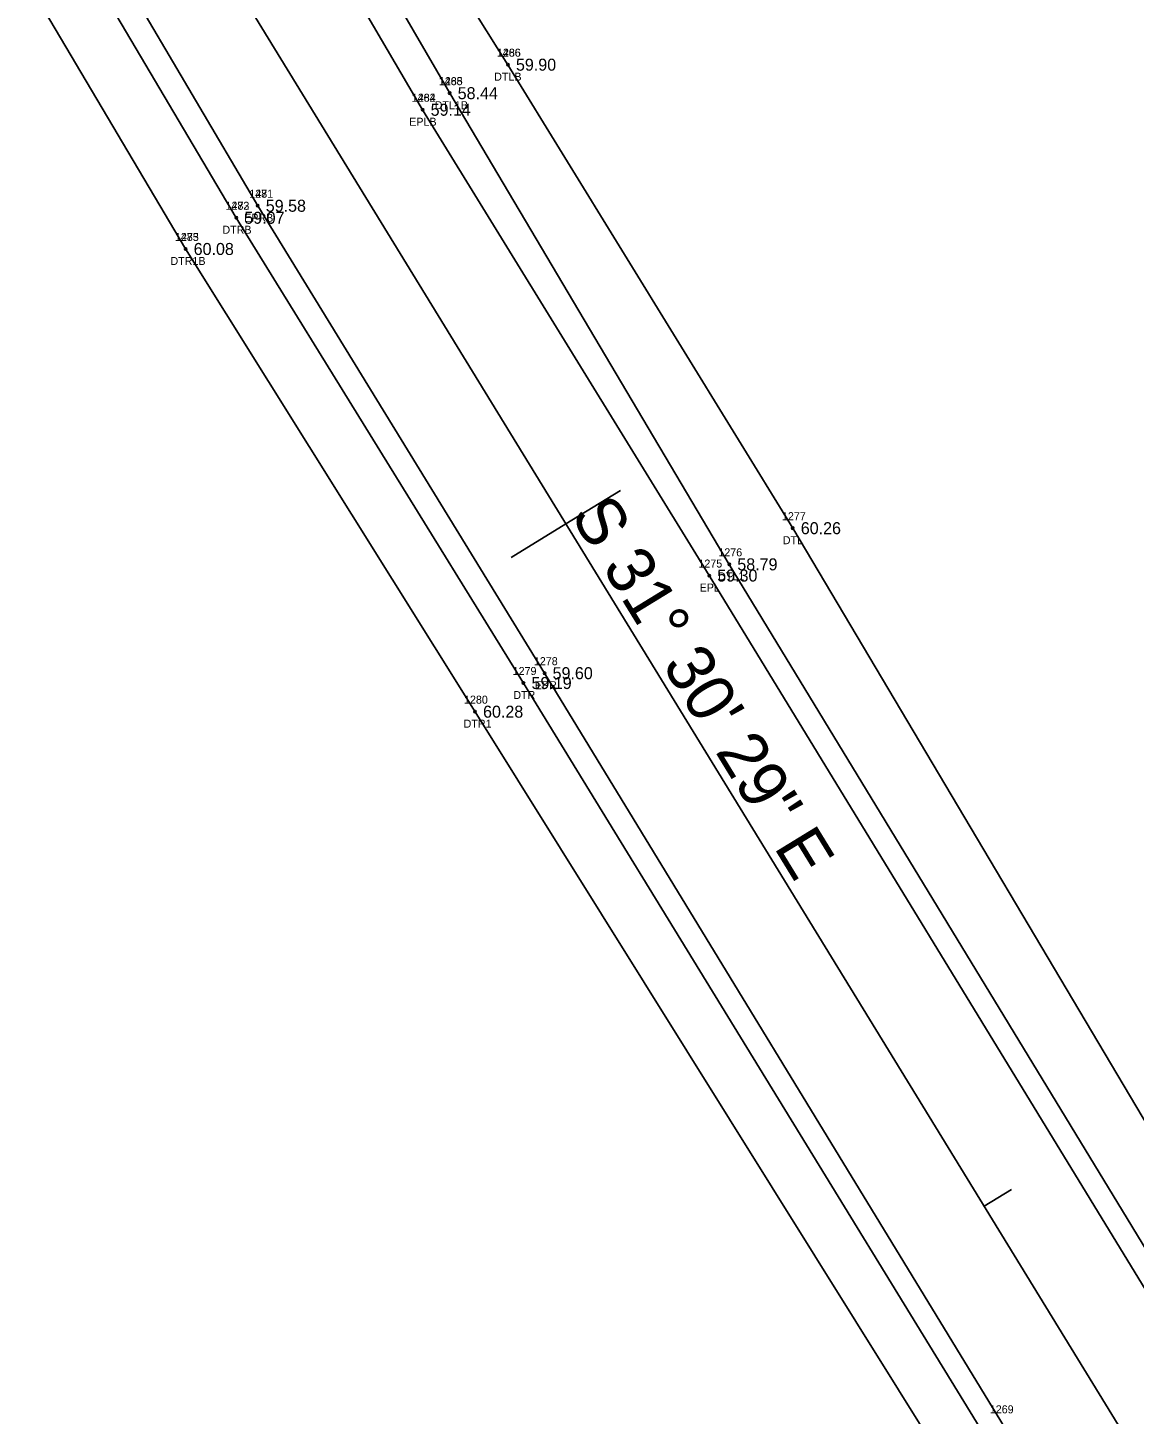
# Model space of a CAD drawing. Extents: x 2396531 to 2397633, y 770203 to 772837.
# Drawn here: x 2397231.4 to 2397369.7, y 770713.7 to 770887 of the extents above; entities that cross this region are included whole.
import ezdxf

# ---------------------------------------------------------------- set-up
doc = ezdxf.new("R2010")
doc.units = 0
for name, color, linetype in [('RD_EX_H2O', 7, 'Continuous'), ('RD_EX_H2O_txCode', 7, 'Continuous'), ('RD_EX_Road', 7, 'Continuous'), ('RD_EX_Road_txCode', 7, 'Continuous'), ('RD_EX_TX_H2O_ELEV', 7, 'Continuous'), ('RD_EX_TX_Road_ELEV', 7, 'Continuous'), ('RD_HC_Cl', 7, 'Continuous'), ('RD_HC_Data', 7, 'Continuous'), ('RD_HC_Data_Tic', 7, 'Continuous'), ('RD_SMD_Locator', 7, 'Continuous')]:
    doc.layers.add(name, color=color, linetype=linetype)

msp = doc.modelspace()

# ---------------------------------------------------------------- linework, layer by layer
at = {"layer": 'RD_EX_H2O'}
msp.add_line((2397255.92, 770938.9), (2397291.42, 770882.36), dxfattribs=at)
for points in [[(2397108.85, 771101.86), (2397130.27, 771108.67), (2397157.99, 771046.03), (2397184.53, 770991.63), (2397224.53, 770918.86), (2397257.48, 770863.23)], [(2397108.85, 771101.86), (2397123.52, 771093.58), (2397147.97, 771040.86), (2397177.5, 770986.79), (2397217.86, 770915.5), (2397251.15, 770859.33)], [(2397255.92, 770938.9), (2397250.75, 770936.23), (2397284.14, 770878.8)], [(2397586.15, 770211.51), (2397567.31, 770287.61), (2397548.79, 770357.79), (2397525.19, 770434.22), (2397495.53, 770510.39), (2397465.51, 770576.5), (2397430.55, 770645.5), (2397380.29, 770734.7), (2397327.01, 770824.44), (2397291.42, 770882.36)], [(2397579.43, 770209.93), (2397561.1, 770285.3), (2397543.19, 770356.19), (2397518.98, 770431.67), (2397489.88, 770507.8), (2397460.56, 770573.86), (2397425.02, 770642.83), (2397373.6, 770730.3), (2397319.08, 770819.92), (2397284.14, 770878.8)], [(2397432.83, 770561.85), (2397399.16, 770627.27), (2397350.75, 770711.42), (2397293.36, 770805.09), (2397257.48, 770863.23)], [(2397432.83, 770561.85), (2397426.86, 770559.56), (2397394.23, 770624.59), (2397345.55, 770708.21), (2397287.31, 770801.51), (2397251.15, 770859.33)]]:
    msp.add_lwpolyline(points, dxfattribs=at)
at = {"layer": 'RD_EX_Road'}
for points in [[(2397113.76, 771228.75), (2397130.87, 771177.98), (2397154.19, 771118.49), (2397170.38, 771081.25), (2397178.53, 771063.49), (2397207.96, 771004.56), (2397238.54, 770949.11), (2397245.72, 770936.59), (2397280.76, 770876.73)], [(2397093.16, 771212.62), (2397108.35, 771171.65), (2397122.66, 771133.29), (2397131.66, 771109.5), (2397159.86, 771046.96), (2397187.02, 770992.86), (2397227.29, 770920.43), (2397260.16, 770864.73)], [(2397576.88, 770209.21), (2397558.85, 770284.47), (2397539.93, 770354.87), (2397515.81, 770430.13), (2397486.97, 770506.75), (2397457.82, 770572.7), (2397422.37, 770641.75), (2397371.16, 770729.12), (2397316.57, 770818.52), (2397280.76, 770876.73)], [(2397553.19, 770205.48), (2397535.12, 770280.96), (2397517, 770349.24), (2397493.4, 770422.78), (2397467.13, 770492.9), (2397441.16, 770551.74), (2397436.66, 770561.67), (2397402.21, 770629.28), (2397353, 770712.83), (2397296, 770806.32), (2397260.16, 770864.73)]]:
    msp.add_lwpolyline(points, dxfattribs=at)
at = {"layer": 'RD_HC_Cl'}
msp.add_line((2397257.22, 770892.58), (2397369.44, 770709.51), dxfattribs=at)
at = {"layer": 'RD_HC_Data_Tic'}
for p, q in [((2397298.66, 770824.97), (2397305.48, 770829.15)), ((2397298.66, 770824.97), (2397291.84, 770820.79)), ((2397350.92, 770739.72), (2397354.33, 770741.81))]:
    msp.add_line(p, q, dxfattribs=at)
at = {"layer": 'RD_SMD_Locator'}
for centre in [(2397291.42, 770882.36), (2397291.42, 770882.36), (2397284.14, 770878.8), (2397284.14, 770878.8), (2397280.76, 770876.73), (2397280.76, 770876.73), (2397260.16, 770864.73), (2397260.16, 770864.73), (2397257.48, 770863.23), (2397257.48, 770863.23), (2397251.15, 770859.33), (2397251.15, 770859.33), (2397327.01, 770824.44), (2397319.08, 770819.92), (2397316.57, 770818.52), (2397296, 770806.32), (2397293.36, 770805.09), (2397287.31, 770801.51)]:
    msp.add_circle(centre, 0.15, dxfattribs=at)

# ---------------------------------------------------------------- texts
at = {"layer": 'RD_EX_H2O_txCode'}
for s, p in [('1466', (2397290.02, 770883.36)), ('1286', (2397290.05, 770883.36)), ('1468', (2397282.77, 770879.8)), ('1285', (2397282.79, 770879.8)), ('DTLB', (2397289.7, 770880.36)), ('DTLB', (2397289.7, 770880.36)), ('DTL1B', (2397282.26, 770876.8)), ('DTL1B', (2397282.26, 770876.8)), ('1282', (2397256.13, 770864.23)), ('1473', (2397256.13, 770864.23)), ('1283', (2397249.81, 770860.33)), ('1475', (2397249.81, 770860.33)), ('DTRB', (2397255.74, 770861.23)), ('DTRB', (2397255.74, 770861.23)), ('DTR1B', (2397249.25, 770857.33)), ('DTR1B', (2397249.25, 770857.33)), ('1277', (2397325.66, 770825.44)), ('DTL', (2397325.76, 770822.44)), ('1276', (2397317.71, 770820.92)), ('DTL1', (2397317.67, 770817.92)), ('1279', (2397292.01, 770806.09)), ('DTR', (2397292.09, 770803.09)), ('1280', (2397285.93, 770802.51)), ('DTR1', (2397285.88, 770799.51))]:
    msp.add_text(s, height=1, dxfattribs=at).set_placement(p)
at = {"layer": 'RD_EX_Road_txCode'}
for s, p in [('1462', (2397279.39, 770877.73)), ('1284', (2397279.41, 770877.73)), ('EPLB', (2397279.08, 770874.73)), ('EPLB', (2397279.08, 770874.73)), ('1281', (2397259.1, 770865.73)), ('1471', (2397259.1, 770865.73)), ('EPRB', (2397258.46, 770862.73)), ('EPRB', (2397258.46, 770862.73)), ('1275', (2397315.22, 770819.52)), ('EPL', (2397315.37, 770816.52)), ('1278', (2397294.66, 770807.32)), ('EPR', (2397294.77, 770804.32)), ('1269', (2397351.63, 770713.83))]:
    msp.add_text(s, height=1, dxfattribs=at).set_placement(p)
at = {"layer": 'RD_EX_TX_H2O_ELEV'}
for s, p in [('59.90', (2397292.42, 770881.61)), ('59.90', (2397292.42, 770881.61)), ('58.44', (2397285.14, 770878.05)), ('58.44', (2397285.14, 770878.05)), ('59.07', (2397258.48, 770862.48)), ('59.07', (2397258.48, 770862.48)), ('60.08', (2397252.15, 770858.58)), ('60.08', (2397252.15, 770858.58)), ('60.26', (2397328.01, 770823.69)), ('58.79', (2397320.08, 770819.17)), ('59.19', (2397294.36, 770804.34)), ('60.28', (2397288.31, 770800.76))]:
    msp.add_text(s, height=1.5, dxfattribs=at).set_placement(p)
at = {"layer": 'RD_EX_TX_Road_ELEV'}
for s, p in [('59.14', (2397281.76, 770875.98)), ('59.14', (2397281.76, 770875.98)), ('59.58', (2397261.16, 770863.98)), ('59.58', (2397261.16, 770863.98)), ('59.30', (2397317.57, 770817.77)), ('59.60', (2397297, 770805.57))]:
    msp.add_text(s, height=1.5, dxfattribs=at).set_placement(p)
at = {"layer": 'RD_HC_Data'}
msp.add_text('S 31%%d 30\' 29" E', height=6, rotation=301.5082, dxfattribs=at).set_placement((2397299.15, 770826.07))

doc.saveas('drawing.dxf')
